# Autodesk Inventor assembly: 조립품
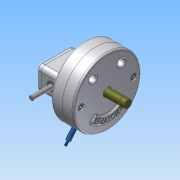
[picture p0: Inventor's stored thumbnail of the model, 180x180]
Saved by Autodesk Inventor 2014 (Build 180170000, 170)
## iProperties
Created: 2015-04
Part Number: 조립품
Document SubType Name: Assembly
Designer: Administrator
Mass: 3883.92 g
Surface Area: 3333.71 cm^2
Volume: 1140.85 cm^3
Density: 3.40441 g/cm^3
Author: Administrator
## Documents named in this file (15)
- C:\Documents and Settings\Administrator\바탕 화면\350406V1022\조립품.iam
- C:\Documents and Settings\Administrator\바탕 화면\350406V1022\본체.ipt
- C:\Documents and Settings\Administrator\바탕 화면\350406V1022\커버2.ipt
- C:\Documents and Settings\Administrator\바탕 화면\350406V1022\커버.ipt
- C:\Documents and Settings\Administrator\바탕 화면\350406V1022\M 10 x 35.ipt
- C:\Documents and Settings\Administrator\바탕 화면\350406V1022\M 5 x 12.ipt
- C:\Documents and Settings\Administrator\바탕 화면\350406V1022\베어링62_22.ipt
- C:\Documents and Settings\Administrator\바탕 화면\350406V1022\축.ipt
- C:\Documents and Settings\Administrator\바탕 화면\350406V1022\멈춤링.ipt
- C:\Documents and Settings\Administrator\바탕 화면\350406V1022\부시.ipt
- C:\Documents and Settings\Administrator\바탕 화면\350406V1022\슬라이더3.ipt
- C:\Documents and Settings\Administrator\바탕 화면\350406V1022\가변스프링.ipt
- C:\Documents and Settings\Administrator\바탕 화면\350406V1022\슬라이더2.ipt
- C:\Documents and Settings\Administrator\바탕 화면\350406V1022\슬라이더.ipt
- C:\Documents and Settings\Administrator\바탕 화면\350406V1022\평행핀.ipt
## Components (6 placed, 4 different names)
1. M 10 x 35:1
2. M 10 x 35:2
3. M 5 x 12:1
4. M 5 x 12:2
5. 가변스프링:1
6. KS B 1320 B B 5 x  20:1 — 플러쉬:1
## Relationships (1: Flush 1)
- 플러쉬:1 [Flush]: KS B 1320 B B 5 x  20:1
